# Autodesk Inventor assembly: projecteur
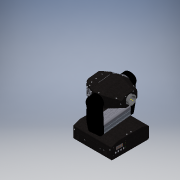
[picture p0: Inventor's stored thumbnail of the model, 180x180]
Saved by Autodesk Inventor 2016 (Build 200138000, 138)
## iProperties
Created: 2011-01
Part Number: projecteur
Document SubType Name: Assembly
Designer: eric
Norme de conversion: IGES 5.3
Nom du fichier: No Iges File Name specified
Préprocesseur: Autodesk Inventor 2011
Postprocesseur: Build: 342, Release: 2008 SP3 - Date: Tue 05/27/2008
Unités envoyées: MM
Incertitude: 0.01
Author: eric
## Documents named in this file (6)
- \\DC1-0210006T\TSTIDD - Ressources\activité 3 projecteur e-move\projecteurimov\projecteur.iam
- \\DC1-0210006T\TSTIDD - Ressources\activité 3 projecteur e-move\projecteurimov\BOITIER.iam
- \\DC1-0210006T\TSTIDD - Ressources\activité 3 projecteur e-move\projecteurimov\Arceau_mobile.iam
- \\DC1-0210006T\TSTIDD - Ressources\activité 3 projecteur e-move\projecteurimov\boitier_projection.iam
- \\DC1-0210006T\TSTIDD - Ressources\activité 3 projecteur e-move\projecteurimov\rotor_moteur.iam
- \\DC1-0210006T\TSTIDD - Ressources\activité 3 projecteur e-move\projecteurimov\rotor_moteur_rotor pan.iam
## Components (5 placed, 5 different names)
1. BOITIER:1 [sub-assembly] — Placage:1, Placage:2, Placage:3, Affleurement:1
2. Arceau_mobile:1 [sub-assembly] — Placage:1, Placage:2, Placage:4, Placage:5, Placage:6, Affleurement:2
3. boitier_projection:1 [sub-assembly] — Placage:5, Placage:6
4. rotor_moteur:1 [sub-assembly] — Placage:4, Affleurement:2
5. rotor_moteur_rotor pan:1 [sub-assembly] — Placage:3, Affleurement:1
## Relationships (8: Mate 6, Flush 2)
- Placage:1 [Mate]: BOITIER:1 ↔ Arceau_mobile:1
- Placage:2 [Mate]: BOITIER:1 ↔ Arceau_mobile:1
- Placage:3 [Mate]: BOITIER:1 ↔ rotor_moteur_rotor pan:1
- Affleurement:1 [Flush]: BOITIER:1 ↔ rotor_moteur_rotor pan:1
- Placage:4 [Mate]: Arceau_mobile:1 ↔ rotor_moteur:1
- Placage:5 [Mate]: Arceau_mobile:1 ↔ boitier_projection:1
- Placage:6 [Mate]: Arceau_mobile:1 ↔ boitier_projection:1
- Affleurement:2 [Flush]: Arceau_mobile:1 ↔ rotor_moteur:1
